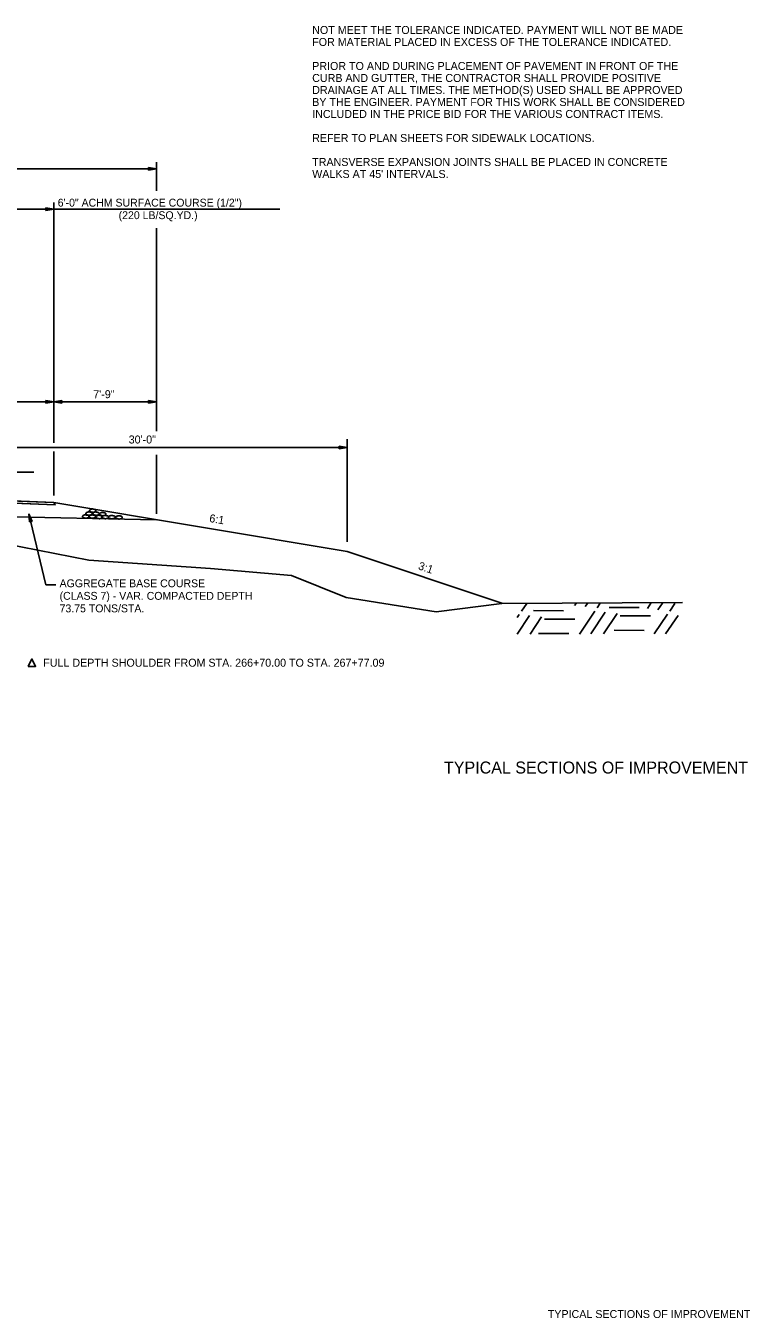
# Model space of a CAD drawing. Extents: x 1001270 to 1003428, y 1840152 to 1842912.
# Drawn here: x 1003372 to 1003426.3, y 1842618.2 to 1842715.1 of the extents above; entities that cross this region are included whole.
import ezdxf

# ---------------------------------------------------------------- set-up
doc = ezdxf.new("R2010")
doc.units = 0
for name, color, linetype in [('1', 7, 'Continuous'), ('19', 7, 'Continuous'), ('60', 7, 'Continuous')]:
    doc.layers.add(name, color=color, linetype=linetype)

# ---------------------------------------------------------------- blocks, each defined once
blk = doc.blocks.new('ROCKS')
at = {"layer": '1'}
blk.add_spline([(0.013, 0.06), (0.053, 0.053), (0.107, 0.033), (0.133, 0.013), (0.133, -0.007), (0.12, -0.033), (0.107, -0.04), (0.073, -0.053), (0.033, -0.067), (0.013, -0.067), (-0.02, -0.06), (-0.06, -0.053), (-0.087, -0.047), (-0.113, -0.02), (-0.113, -0.007), (-0.107, 0.02), (-0.087, 0.033), (-0.067, 0.047), (-0.033, 0.053), (-0.02, 0.06), (0.013, 0.06)], degree=3, dxfattribs=at)
blk = doc.blocks.new('4TO1 ABC')
at = {"layer": '1', "xscale": 0.1312491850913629, "yscale": 0.1312491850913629, "rotation": 180}
for p in [(0.00175, -0.00875), (-0.03325, -0.0385), (-0.016625, -0.023625), (0, -0.0385), (0.018375, -0.023625), (0.034125, -0.04025), (0.051625, -0.025375), (0.06475, -0.04025), (0.098, -0.04025), (0.133, -0.041125)]:
    blk.add_blockref('ROCKS', p, dxfattribs=at)

msp = doc.modelspace()

# ---------------------------------------------------------------- linework, layer by layer
at = {"layer": '19'}
for p, q in [((1003381.798, 1842702.778), (1003381.798, 1842704.922)), ((1003314.389, 1842704.422), (1003381.798, 1842704.422)), ((1003381.198, 1842704.317), (1003381.198, 1842704.527)), ((1003381.198, 1842704.527), (1003381.798, 1842704.422)), ((1003381.198, 1842704.472), (1003381.638, 1842704.437)), ((1003381.798, 1842704.422), (1003381.198, 1842704.317)), ((1003381.638, 1842704.407), (1003381.198, 1842704.367)), ((1003305.147, 1842701.395), (1003391.043, 1842701.395)), ((1003373.494, 1842701.29), (1003373.494, 1842701.5)), ((1003373.494, 1842701.5), (1003374.094, 1842701.395)), ((1003373.494, 1842701.445), (1003373.934, 1842701.41)), ((1003374.094, 1842701.395), (1003373.494, 1842701.29)), ((1003373.934, 1842701.38), (1003373.494, 1842701.34)), ((1003374.094, 1842683.866), (1003374.094, 1842701.895)), ((1003381.798, 1842684.761), (1003381.798, 1842699.974)), ((1003381.798, 1842686.946), (1003366.094, 1842686.946)), ((1003373.494, 1842686.841), (1003373.494, 1842687.051)), ((1003373.494, 1842687.051), (1003374.094, 1842686.946)), ((1003373.494, 1842686.996), (1003373.934, 1842686.961)), ((1003374.094, 1842686.946), (1003373.494, 1842686.841)), ((1003373.934, 1842686.931), (1003373.494, 1842686.891)), ((1003374.694, 1842687.051), (1003374.094, 1842686.946)), ((1003374.094, 1842686.946), (1003374.694, 1842686.841)), ((1003374.694, 1842686.996), (1003374.254, 1842686.961)), ((1003374.254, 1842686.931), (1003374.694, 1842686.891)), ((1003374.694, 1842686.841), (1003374.694, 1842687.051)), ((1003381.198, 1842686.841), (1003381.198, 1842687.051)), ((1003381.198, 1842687.051), (1003381.798, 1842686.946)), ((1003381.198, 1842686.996), (1003381.638, 1842686.961)), ((1003381.798, 1842686.946), (1003381.198, 1842686.841)), ((1003381.638, 1842686.931), (1003381.198, 1842686.891)), ((1003395.494, 1842683.422), (1003395.494, 1842683.632)), ((1003395.494, 1842683.632), (1003396.094, 1842683.527)), ((1003396.094, 1842676.46), (1003396.094, 1842684.16)), ((1003396.094, 1842683.527), (1003366.094, 1842683.527)), ((1003374.094, 1842679.918), (1003374.094, 1842683.229)), ((1003381.798, 1842678.559), (1003381.798, 1842682.977)), ((1003395.494, 1842683.577), (1003395.934, 1842683.542)), ((1003396.094, 1842683.527), (1003395.494, 1842683.422)), ((1003395.934, 1842683.512), (1003395.494, 1842683.472)), ((1003372.575, 1842681.665), (1003363.267, 1842681.665)), ((1003348.094, 1842678.786), (1003381.798, 1842678.112)), ((1003368.094, 1842679.636), (1003374.094, 1842679.396)), ((1003368.094, 1842679.469), (1003374.179, 1842679.226)), ((1003396.094, 1842675.729), (1003374.094, 1842679.396)), ((1003374.094, 1842679.396), (1003374.179, 1842679.226)), ((1003372.26, 1842677.943), (1003372.223, 1842678.549)), ((1003372.223, 1842678.549), (1003372.463, 1842677.989)), ((1003373.482, 1842673.237), (1003372.223, 1842678.549)), ((1003372.308, 1842677.955), (1003372.244, 1842678.39)), ((1003372.463, 1842677.989), (1003372.26, 1842677.943)), ((1003372.272, 1842678.397), (1003372.411, 1842677.98)), ((1003396.094, 1842675.729), (1003407.685, 1842671.865)), ((1003374.249, 1842673.237), (1003373.482, 1842673.237)), ((1003408.831, 1842670.785), (1003408.985, 1842671.01)), ((1003409.171, 1842671.252), (1003409.562, 1842671.835)), ((1003410.059, 1842671.292), (1003412.319, 1842671.27)), ((1003413.156, 1842671.687), (1003413.262, 1842671.837)), ((1003413.508, 1842669.539), (1003414.66, 1842671.26)), ((1003413.951, 1842671.595), (1003414.117, 1842671.839)), ((1003414.363, 1842669.542), (1003415.455, 1842671.169)), ((1003414.846, 1842671.503), (1003415.072, 1842671.841)), ((1003415.318, 1842669.544), (1003416.35, 1842671.077)), ((1003415.734, 1842671.532), (1003417.994, 1842671.521)), ((1003418.61, 1842671.447), (1003418.872, 1842671.842)), ((1003419.118, 1842669.545), (1003420.114, 1842671.021)), ((1003419.405, 1842671.355), (1003419.737, 1842671.844)), ((1003420.3, 1842671.263), (1003420.681, 1842671.837)), ((1003408.853, 1842669.536), (1003409.78, 1842670.918)), ((1003409.808, 1842669.538), (1003410.675, 1842670.826)), ((1003410.899, 1842670.662), (1003413.159, 1842670.641)), ((1003416.564, 1842670.904), (1003418.834, 1842670.891)), ((1003419.973, 1842669.548), (1003420.909, 1842670.929)), ((1003410.446, 1842669.583), (1003412.717, 1842669.571)), ((1003416.122, 1842669.833), (1003418.382, 1842669.812))]:
    msp.add_line(p, q, dxfattribs=at)
for points in [[(1003374.094, 1842679.396), (1003374.179, 1842679.226), (1003368.094, 1842679.469), (1003368.094, 1842679.636)], [(1003372.157, 1842667.107), (1003372.439, 1842667.67), (1003372.72, 1842667.107)]]:
    msp.add_lwpolyline(points, close=True, dxfattribs=at)
msp.add_lwpolyline([(1003277.614, 1842677.159), (1003281.998, 1842677.23), (1003287.741, 1842677.06), (1003292.478, 1842677.542), (1003299.632, 1842677.226), (1003306.993, 1842676.318), (1003322.358, 1842675.803), (1003333.488, 1842675.604), (1003338.274, 1842676.432), (1003352.72, 1842676.291), (1003358.998, 1842675.251), (1003364.235, 1842675.775), (1003366.532, 1842675.647), (1003370.336, 1842676.334), (1003376.702, 1842675.08), (1003385.85, 1842674.465), (1003391.912, 1842673.921), (1003396.022, 1842672.287), (1003402.77, 1842671.198), (1003407.685, 1842671.825), (1003421.251, 1842671.899)], dxfattribs=at)

# ---------------------------------------------------------------- block references
at = {"layer": '19', "xscale": 14.999970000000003, "yscale": 14.999970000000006, "rotation": -0.5653128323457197}
msp.add_blockref('4TO1 ABC', (1003376.995, 1842678.917), dxfattribs=at)

# ---------------------------------------------------------------- texts
at = {"layer": '1'}
msp.add_text('TYPICAL SECTIONS OF IMPROVEMENT', height=0.6, dxfattribs=at).set_placement((1003411.138, 1842618.242))
msp.add_text('TYPICAL SECTIONS OF IMPROVEMENT', height=0.6, dxfattribs=at).set_placement((1003411.138, 1842618.242))
at = {"layer": '19'}
for s, height, p in [('NOT MEET THE TOLERANCE INDICATED. PAYMENT WILL NOT BE MADE', 0.6, (1003393.468, 1842714.539)), ('FOR MATERIAL PLACED IN EXCESS OF THE TOLERANCE INDICATED.', 0.6, (1003393.468, 1842713.639)), ('PRIOR TO AND DURING PLACEMENT OF PAVEMENT IN FRONT OF THE', 0.6, (1003393.468, 1842711.839)), ('CURB AND GUTTER, THE CONTRACTOR SHALL PROVIDE POSITIVE', 0.6, (1003393.468, 1842710.939)), ('DRAINAGE AT ALL TIMES. THE METHOD(S) USED SHALL BE APPROVED', 0.6, (1003393.468, 1842710.039)), ('BY THE ENGINEER. PAYMENT FOR THIS WORK SHALL BE CONSIDERED', 0.6, (1003393.468, 1842709.139)), ('INCLUDED IN THE PRICE BID FOR THE VARIOUS CONTRACT ITEMS.', 0.6, (1003393.468, 1842708.239)), ('REFER TO PLAN SHEETS FOR SIDEWALK LOCATIONS.', 0.6, (1003393.468, 1842706.439)), ('TRANSVERSE EXPANSION JOINTS SHALL BE PLACED IN CONCRETE', 0.6, (1003393.468, 1842704.639)), ("WALKS AT 45' INTERVALS.", 0.6, (1003393.468, 1842703.739)), ('6\'-0" ACHM SURFACE COURSE (1/2")', 0.59001, (1003374.379, 1842701.593)), ('(220 LB/SQ.YD.)', 0.59001, (1003378.95, 1842700.653)), ('7\'-9"', 0.6, (1003377.044, 1842687.225)), ('30\'-0"', 0.6, (1003379.702, 1842683.827))]:
    msp.add_text(s, height=height, dxfattribs=at).set_placement(p)
for s, height, rotation, p in [('6:1', 0.6, 350.60768, (1003385.718, 1842677.946)), ('3:1', 0.6, 341.56505, (1003401.371, 1842674.407)), ('AGGREGATE BASE COURSE', 0.59001, 359.99538, (1003374.519, 1842673.047)), ('(CLASS 7) - VAR. COMPACTED DEPTH', 0.59001, 359.99538, (1003374.519, 1842672.107)), ('73.75 TONS/STA.', 0.59001, 359.99538, (1003374.518, 1842671.167)), ('FULL DEPTH SHOULDER FROM STA. 266+70.00 TO STA. 267+77.09', 0.6, 359.99538, (1003373.292, 1842667.088))]:
    msp.add_text(s, height=height, rotation=rotation, dxfattribs=at).set_placement(p)
at = {"layer": '60'}
msp.add_text('TYPICAL SECTIONS OF IMPROVEMENT', height=0.9, dxfattribs=at).set_placement((1003403.354, 1842659.077))
msp.add_text('TYPICAL SECTIONS OF IMPROVEMENT', height=0.9, dxfattribs=at).set_placement((1003403.354, 1842659.077))

doc.saveas('drawing.dxf')
